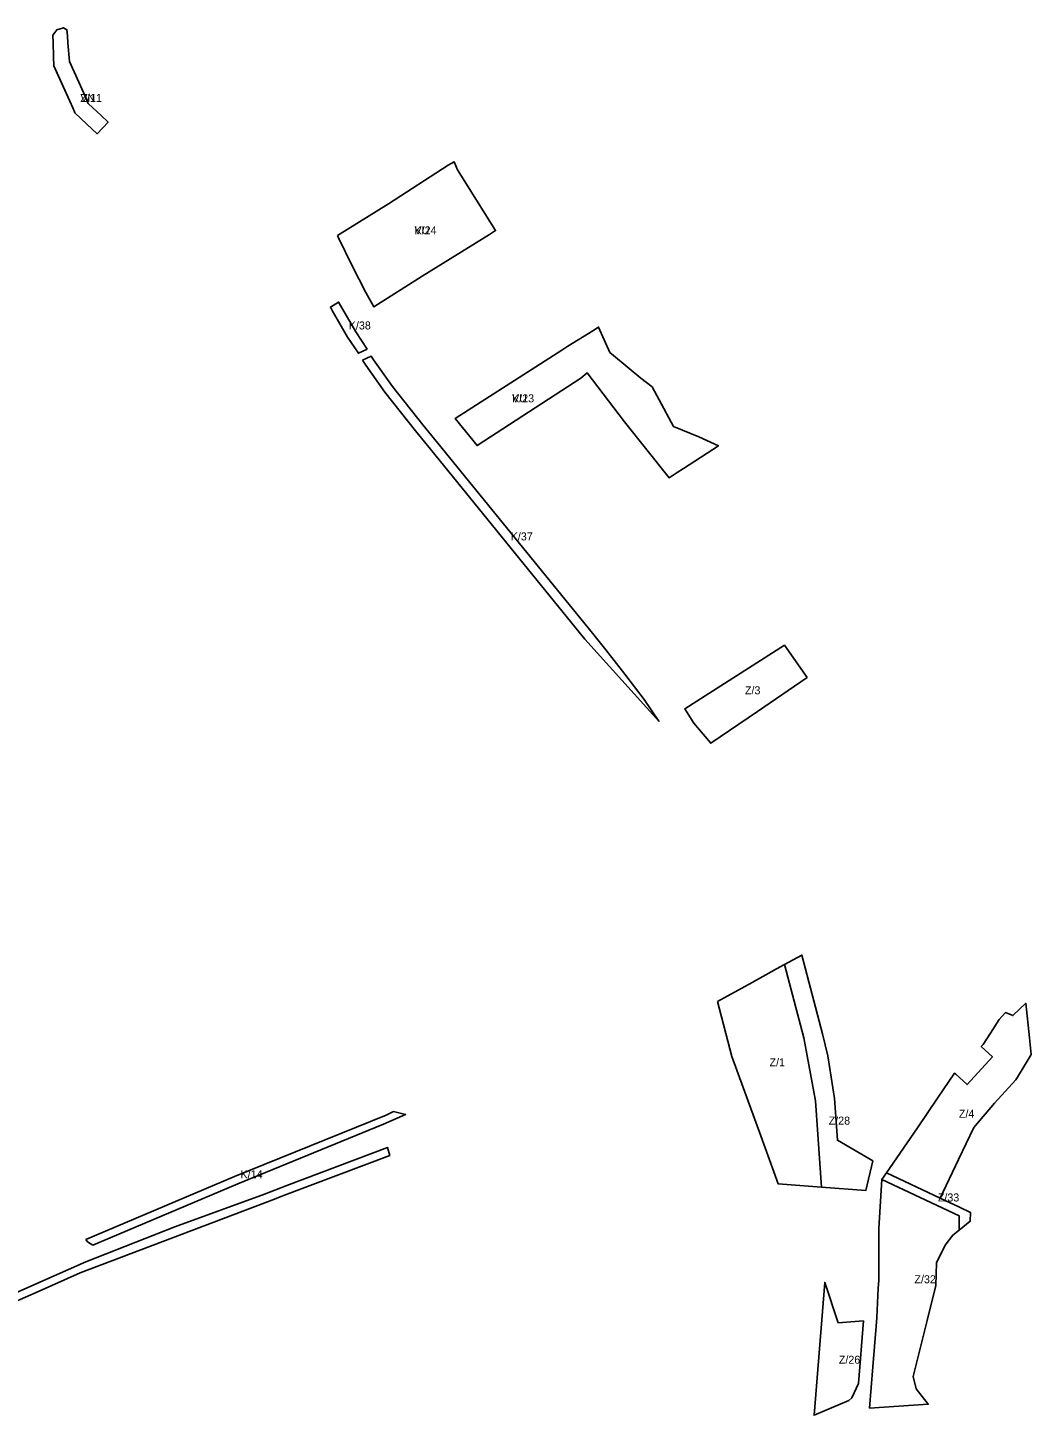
# Model space of a CAD drawing. Extents: x -521969 to -519862, y -1142171 to -1140238.
# Drawn here: x -521119 to -520491, y -1141105 to -1140238 of the extents above; entities that cross this region are included whole.
import ezdxf

# ---------------------------------------------------------------- set-up
doc = ezdxf.new("R2010")
doc.units = 0
for name, color, linetype in [('95420023', 7, 'Continuous'), ('96111023', 7, 'Continuous'), ('96141023', 7, 'Continuous'), ('96202423', 7, 'Continuous')]:
    doc.layers.add(name, color=color, linetype=linetype)

msp = doc.modelspace()

# ---------------------------------------------------------------- linework, layer by layer
at = {"layer": '95420023'}
for points in [[(-521102.93, -1140242.86), (-521100.42, -1140239.62), (-521096.26, -1140238.22), (-521094.12, -1140239.48), (-521093.8, -1140243.17), (-521093.43, -1140247.58), (-521092.42, -1140259.41), (-521083.79, -1140278.7), (-521081.89, -1140282.94), (-521081.11, -1140284.7), (-521080.73, -1140285.54), (-521072.76, -1140293.07), (-521068.35, -1140297.23), (-521075.22, -1140304.5), (-521081.54, -1140298.53), (-521089.05, -1140291.44), (-521089.34, -1140290.78), (-521090.43, -1140288.34), (-521092.32, -1140284.11), (-521102.24, -1140261.94), (-521102.44, -1140256.49), (-521102.76, -1140247.73)], [(-520631.48, -1140644.23), (-520662.52, -1140665.44), (-520691.74, -1140685.4), (-520702.26, -1140672.84), (-520707.94, -1140663.79), (-520645.69, -1140624.14)], [(-520687.49, -1140846.81), (-520665.74, -1140834.79), (-520650.7, -1140826.31), (-520645.66, -1140823.61), (-520633.62, -1140869.48), (-520626.29, -1140908.87), (-520622.44, -1140962.75), (-520649.51, -1140960.76), (-520660.47, -1140930.63), (-520678.48, -1140881.15)], [(-520622.44, -1140962.75), (-520626.29, -1140908.87), (-520633.62, -1140869.48), (-520645.66, -1140823.61), (-520634.79, -1140817.77), (-520621.9, -1140866.86), (-520618.56, -1140880.81), (-520614.37, -1140907.34), (-520612.5, -1140933.48), (-520590.36, -1140946.34), (-520594.75, -1140964.79)], [(-520521.46, -1140873.68), (-520516.84, -1140866.53), (-520511.48, -1140857.9), (-520507.49, -1140853.67), (-520502.85, -1140855.53), (-520494.89, -1140847.8), (-520492.53, -1140869.55), (-520491.41, -1140879.85), (-520497.04, -1140889.19), (-520500.98, -1140895.73), (-520514.41, -1140910.27), (-520527.38, -1140925.42), (-520536.98, -1140945.57), (-520548.43, -1140969.6), (-520581.88, -1140953.8), (-520562.58, -1140925.73), (-520549.95, -1140907.16), (-520539.31, -1140891.51), (-520538.57, -1140892.18), (-520531.52, -1140898.7), (-520515.64, -1140881.37), (-520522.62, -1140874.92)], [(-520581.88, -1140953.8), (-520548.43, -1140969.6), (-520536.34, -1140975.31), (-520529.45, -1140978.56), (-520529.52, -1140984.06), (-520536.52, -1140989.65), (-520536.41, -1140980.8), (-520560.76, -1140969.3), (-520584.75, -1140957.97)], [(-520536.52, -1140989.65), (-520540.36, -1140992.71), (-520545.15, -1140999.12), (-520550.66, -1141010.15), (-520551.07, -1141024.16), (-520556.5, -1141046.1), (-520561.24, -1141065.24), (-520565.18, -1141081.15), (-520563.4, -1141088.78), (-520555.74, -1141098.46), (-520592.43, -1141100.83), (-520590.32, -1141074.97), (-520588.29, -1141049.68), (-520587.85, -1141044.25), (-520586.99, -1141025.98), (-520586.76, -1141021.16), (-520586.68, -1140988.64), (-520584.75, -1140957.97), (-520560.76, -1140969.3), (-520536.41, -1140980.8)], [(-520596.21, -1141046.3), (-520599.33, -1141085.41), (-520603.47, -1141094.45), (-520605.48, -1141096), (-520627.13, -1141105.32), (-520620.51, -1141022.34), (-520612.04, -1141047.58)]]:
    msp.add_lwpolyline(points, close=True, dxfattribs=at)
at = {"layer": '96111023'}
for points in [[(-520925.04, -1140368.05), (-520893.13, -1140348.26), (-520855.89, -1140324.19), (-520852.13, -1140321.93), (-520849.95, -1140326.96), (-520826.19, -1140365.01), (-520830.07, -1140367.42), (-520872.15, -1140393.54), (-520902.19, -1140412.67), (-520907.24, -1140403.74), (-520915.77, -1140387.04), (-520924.44, -1140369.44)], [(-520906.37, -1140439.12), (-520911.89, -1140441.66), (-520918.68, -1140431.5), (-520928.3, -1140414.82), (-520929.42, -1140412.75), (-520924.28, -1140409.64), (-520923.06, -1140411.9), (-520913.58, -1140428.33)], [(-520784.75, -1140439.67), (-520781.06, -1140437.3), (-520765.49, -1140427.57), (-520761.78, -1140425.25), (-520754.76, -1140441.12), (-520752.54, -1140443.09), (-520735.34, -1140457.3), (-520728.4, -1140462.65), (-520724, -1140470.78), (-520714.97, -1140487.48), (-520699.14, -1140493.81), (-520686.89, -1140499.45), (-520708.82, -1140513.67), (-520712.75, -1140516.21), (-520717.71, -1140519.42), (-520745.68, -1140484.57), (-520769.04, -1140453.82), (-520772.84, -1140457.31), (-520837.71, -1140499.35), (-520851.49, -1140482.48)], [(-520909.31, -1140446.06), (-520903.84, -1140443.54), (-520902.4, -1140445.74), (-520890.58, -1140462.46), (-520871.65, -1140486.28), (-520862.22, -1140497.87), (-520765.71, -1140616.57), (-520757.18, -1140627.06), (-520745.42, -1140642.26), (-520733.42, -1140657.97), (-520724.12, -1140671.61), (-520770.37, -1140620.36), (-520866.87, -1140501.66), (-520876.33, -1140490.04), (-520895.38, -1140466.06), (-520907.36, -1140449.12), (-520908.96, -1140446.68)], [(-521082.3, -1140995.42), (-520989.26, -1140956.04), (-520894.6, -1140917.89), (-520890.08, -1140915.49), (-520882.47, -1140917.37), (-520896.33, -1140923.45), (-520987.34, -1140960.66), (-521077.97, -1140999.02), (-521081.12, -1140996.97)]]:
    msp.add_lwpolyline(points, close=True, dxfattribs=at)
msp.add_lwpolyline([(-521155.63, -1141041.85), (-521112.83, -1141022.98), (-521082.18, -1141009.47), (-521026.59, -1140987.63), (-520970.5, -1140967.09), (-520956.56, -1140961.79), (-520893.74, -1140937.98), (-520892.3, -1140942.89), (-520959.78, -1140968.46), (-520964.29, -1140970.32), (-521085.77, -1141016.42), (-521111.47, -1141027.75), (-521154.28, -1141046.62)], dxfattribs=at)
at = {"layer": '96141023'}
for points in [[(-520925.04, -1140368.05), (-520893.13, -1140348.26), (-520855.89, -1140324.19), (-520852.13, -1140321.93), (-520849.95, -1140326.96), (-520826.19, -1140365.01), (-520830.07, -1140367.42), (-520872.15, -1140393.54), (-520902.19, -1140412.67), (-520907.24, -1140403.74), (-520915.77, -1140387.04), (-520924.44, -1140369.44)], [(-520781.06, -1140437.3), (-520765.49, -1140427.57), (-520761.78, -1140425.25), (-520754.76, -1140441.12), (-520752.54, -1140443.09), (-520735.34, -1140457.3), (-520728.4, -1140462.65), (-520724, -1140470.78), (-520714.97, -1140487.48), (-520699.14, -1140493.81), (-520686.89, -1140499.45), (-520708.82, -1140513.67), (-520712.75, -1140516.21), (-520717.71, -1140519.42), (-520745.68, -1140484.57), (-520769.04, -1140453.82), (-520772.84, -1140457.31), (-520837.71, -1140499.35), (-520851.49, -1140482.48), (-520784.75, -1140439.67)]]:
    msp.add_lwpolyline(points, close=True, dxfattribs=at)
at = {"layer": '96202423'}
msp.add_lwpolyline([(-521092.32, -1140284.11), (-521100.5, -1140265.83), (-521102.24, -1140261.94), (-521102.44, -1140256.49), (-521102.76, -1140247.73), (-521102.93, -1140242.86), (-521100.42, -1140239.62), (-521096.26, -1140238.22), (-521094.12, -1140239.48), (-521093.8, -1140243.17), (-521093.43, -1140247.58), (-521092.42, -1140259.41), (-521083.79, -1140278.7), (-521081.89, -1140282.94), (-521081.11, -1140284.7), (-521080.73, -1140285.54), (-521072.76, -1140293.07), (-521068.35, -1140297.23), (-521075.22, -1140304.5), (-521081.54, -1140298.53), (-521089.05, -1140291.44), (-521089.34, -1140290.78), (-521090.43, -1140288.34)], close=True, dxfattribs=at)

# ---------------------------------------------------------------- texts
at = {"layer": '95420023'}
for s, rotation, p in [('Z/11', 360, (-521085.64, -1140284.61)), ('Z/3', 360, (-520670.34, -1140654.77)), ('Z/1', 0, (-520654.97, -1140887.24)), ('Z/28', 0, (-520618.01, -1140923.68)), ('Z/4', 0, (-520536.64, -1140919.41)), ('Z/33', 360, (-520549.78, -1140971.72)), ('Z/32', 0, (-520564.42, -1141022.83)), ('Z/26', 360, (-520611.67, -1141073.11))]:
    msp.add_text(s, height=5, rotation=rotation, dxfattribs=at).set_placement(p)
at = {"layer": '96111023'}
for s, rotation, p in [('K/24', 0, (-520876.85, -1140367.3)), ('K/38', 0, (-520917.9, -1140426.76)), ('K/23', 0, (-520815.85, -1140472.33)), ('K/37', 360, (-520816.71, -1140558.6)), ('K/14', 360, (-520985.57, -1140957.25))]:
    msp.add_text(s, height=5, rotation=rotation, dxfattribs=at).set_placement(p)
at = {"layer": '96141023'}
for p in [(-520876.85, -1140367.3), (-520815.85, -1140472.33)]:
    msp.add_text('VU', height=5, rotation=0, dxfattribs=at).set_placement(p)
at = {"layer": '96202423'}
msp.add_text('VN', height=5, rotation=360, dxfattribs=at).set_placement((-521085.64, -1140284.61))

doc.saveas('drawing.dxf')
